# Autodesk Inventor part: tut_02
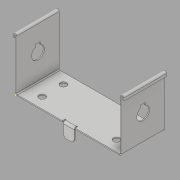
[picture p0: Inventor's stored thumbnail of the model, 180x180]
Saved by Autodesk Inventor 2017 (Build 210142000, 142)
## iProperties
Created: 2015-06
Part Number: tut_02
Material: Generic
Document SubType Name: Sheet Metal
Designer: Sandeep
Density: 1 g/cm^3
Sheet Metal Rule: Default_mm
Appearance: Default
Flat Pattern Width: 5.12619 cm
Flat Pattern Length: 20.443 cm
Flat Pattern Area: 104.795 cm^2
Sheet Metal Width: 51.262 mm
Sheet Metal Length: 204.430 mm
Sheet Metal Area: 10479.484 mm^2
Author: Sandeep
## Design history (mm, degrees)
sketch "Sketch1"
  geometry: 1 further point
node "Face1"
  sketch "Sketch2"
    geometry: L1 (0, 0)-(100, 0); L2 (100, 0)-(100, 40); L3 (100, 40)-(0, 40); L4 (0, 40)-(0, 0)
    constraints: 8 end point, 2 parallel, 1 horizontal, 1 perpendicular
    dimensions: "d0" = 100 distance between parallel lines of L2 L4; "d1" = 40 distance between parallel lines of L1 L3
hole "Hole1" diameter "d5" = 6; stored, may be unused: countersink angle "d9" = 90 deg, drill point angle "d11" = 118 deg; dims "d3" = 10, "d4" = 15, "d6" = 6, "d7" = 4, "d8" = 2, "d10" = 1 (= Thickness)
pattern_linear "Rectangular Pattern1" dims "d14" = 20
pattern_linear "Rectangular Pattern2" dims "d17" = 70
node "Flange1"
node "Flange2"
feature "Hem1" dims "d38" = 1 (= BendReliefWidth), "d39" = 0.5 (= BendReliefDepth), "d40" = 2 (= MinimumRemnant), "d41" = 1 (= BendRadius), "d42" = 4 (= 4 x Thickness), "d43" = 1 (= Thickness), "d44" = 0.5 (= 0.5 x d43), "SeamGap" = 0.01, "Thickness" = 1 (derived)
feature "Hem2" dims "d45" = 1 (= BendReliefWidth), "d46" = 0.5 (= BendReliefDepth), "d47" = 2 (= MinimumRemnant), "d48" = 1 (= BendRadius), "d49" = 4 (= 4 x Thickness), "d50" = 1 (= Thickness), "d51" = 0.5 (= 0.5 x d50), "SeamGap" = 0.01, "Thickness" = 1 (derived)
sketch "Sketch7"
  geometry: L1 (0, 40)-(0, 0) reference; L2 (48, 0)-(0, 0) reference; 2 further points
  dimensions: "d52" = 25 distance from line of point (25, 20) L1; "d53" = 20 distance from line of L2 point (25, 20)
feature "iFeature15:1" sketch "Sketch7"
sketch "Sketch8"
  geometry: L1 (17.2, 18)-(17.2, 22) reference; L2 (19.343, 18)-(17.2, 18) reference; L3 (17.2, 22)-(19.343, 22) reference; L4 (17.2, 18)-(17.2, 22) reference; L5 (17.2, 22)-(19.343, 22) reference; L6 (19.343, 18)-(17.2, 18) reference; L7 (48, 0)-(48, 40) reference; L8 (48, 40)-(1.5, 40) reference; L9 (48, 0)-(1.5, 0) reference; L10 (1.5, 40)-(1.5, 0) reference; A1 r 6 centre (25, 20) between (19.343, 18) and (19.343, 22) reference; A2 r 6 centre (25, 20) between (19.343, 18) and (19.343, 22) reference; 1 further point
feature "iFeature15:2" sketch "Sketch8"
node "Flange3"
feature "Corner Round1" dims "d78" = 3
workplane "Work Plane1"
mirror "Mirror1"
body "Solid1"
face "Plate1" dims "Thickness" = 1 (derived)
sketch "Sketch3"
  geometry: L1 through (20, 0) direction (-1, 0); L2 through (0, -25) direction (0, -1); L3 (0, -50)-(40, -50); L4 (40, -50)-(40, 0)
  constraints: 6 end point, 1 horizontal, 1 perpendicular, 1 vertical
face "Plate2" dims "d18" = 1 (= BendReliefWidth), "d19" = 0.5 (= BendReliefDepth), "d20" = 2 (= MinimumRemnant), "d21" = 1 (= BendRadius), "d22" = 50, "d23" = 90 deg, "d24" = 1 (= BendRadius), "d25" = 4 (= CornerReliefSize), "d26" = 1 (= GapSize), "d27" = 1 (= JacobiRadiusSize), "SeamGap" = 0.01, "Thickness" = 1 (derived)
bend "Bend1" dims "d18" = 1 (= BendReliefWidth), "d19" = 0.5 (= BendReliefDepth), "d20" = 2 (= MinimumRemnant), "d21" = 1 (= BendRadius), "d22" = 50, "d23" = 90 deg, "d24" = 1 (= BendRadius), "SeamGap" = 0.01, "Thickness" = 1 (derived)
feature "Corner1" dims "d22" = 50, "d23" = 90 deg, "d25" = 4 (= CornerReliefSize), "d26" = 1 (= GapSize), "d27" = 1 (= JacobiRadiusSize)
sketch "Sketch4"
  geometry: L1 through (20, 0) direction (-1, 5.47e-48); L2 through (0, -25) direction (-2.71e-32, -1); L3 (0, -50)-(40, -50); L4 (40, -50)-(40, 0)
  constraints: 6 end point, 1 horizontal, 1 perpendicular, 1 vertical
face "Plate3" dims "d28" = 1 (= BendReliefWidth), "d29" = 0.5 (= BendReliefDepth), "d30" = 2 (= MinimumRemnant), "d31" = 1 (= BendRadius), "d32" = 50, "d33" = 90 deg, "d34" = 1 (= BendRadius), "d35" = 4 (= CornerReliefSize), "d36" = 1 (= GapSize), "d37" = 1 (= JacobiRadiusSize), "SeamGap" = 0.01, "Thickness" = 1 (derived)
bend "Bend2" dims "d28" = 1 (= BendReliefWidth), "d29" = 0.5 (= BendReliefDepth), "d30" = 2 (= MinimumRemnant), "d31" = 1 (= BendRadius), "d32" = 50, "d33" = 90 deg, "d34" = 1 (= BendRadius), "SeamGap" = 0.01, "Thickness" = 1 (derived)
feature "Corner2" dims "d32" = 50, "d33" = 90 deg, "d35" = 4 (= CornerReliefSize), "d36" = 1 (= GapSize), "d37" = 1 (= JacobiRadiusSize)
node "Projected Loop1"
sketch "Sketch9"
  geometry: L1 (-53, 0)-(-43, 0); L2 (-43, 0)-(-43, 13); L3 (-43, 13)-(-53, 13); L4 (-53, 13)-(-53, 0)
  constraints: 8 end point
face "Plate4" dims "d67" = 1 (= BendReliefWidth), "d68" = 0.5 (= BendReliefDepth), "d69" = 2 (= MinimumRemnant), "d70" = 1 (= BendRadius), "d71" = 10, "d72" = 13, "d73" = 90 deg, "d74" = 1 (= BendRadius), "d75" = 4 (= CornerReliefSize), "d76" = 1 (= GapSize), "d77" = 1 (= JacobiRadiusSize), "SeamGap" = 0.01, "Thickness" = 1 (derived)
bend "Bend3" dims "d67" = 1 (= BendReliefWidth), "d68" = 0.5 (= BendReliefDepth), "d69" = 2 (= MinimumRemnant), "d70" = 1 (= BendRadius), "d72" = 13, "d73" = 90 deg, "d74" = 1 (= BendRadius), "SeamGap" = 0.01, "Thickness" = 1 (derived)
feature "Corner3" dims "d72" = 13, "d73" = 90 deg, "d75" = 4 (= CornerReliefSize), "d76" = 1 (= GapSize), "d77" = 1 (= JacobiRadiusSize)
sketch "Sketch5"
  geometry: L1 (1, 0)-(0, 0); L2 (-1, 0)-(-1, -2.5); L3 (-1, -2.5)-(-2, -2.5); L4 (-2, -2.5)-(-2, 0); A1 r 0.5 centre (-0.5, 0) between (0, 0) and (-1, 0); A2 r 1.5 centre (-0.5, 0) between (1, 0) and (-2, 0); 2 further points
  constraints: 8 end point, 4 point on circle
sketch "Sketch6"
  geometry: L1 (0, 0)-(1, 0); L2 (2, 0)-(2, -2.5); L3 (2, -2.5)-(3, -2.5); L4 (3, -2.5)-(3, 0); A1 r 0.5 centre (1.5, 0) between (2, 0) and (1, 0); A2 r 1.5 centre (1.5, 0) between (3, 0) and (0, 0); 2 further points
  constraints: 8 end point, 4 point on circle
feature "Definition1"
other parameters: "BendRadius" = 1 (= Thickness), "BendReliefWidth" = 1 (= Thickness), "BendReliefDepth" = 0.5 (= 0.5 x Thickness), "CornerReliefSize" = 4 (= 4 x Thickness), "MinimumRemnant" = 2 (= 2 x Thickness), "TransitionRadius" = 1 (= BendRadius), "JacobiRadiusSize" = 1 (= BendRadius), "GapSize" = 1 (= Thickness), "d2" = 1 (= BendRadius), "d66" = 90 deg, "d81" = 90 deg, "BendRadius" = 1, "BendReliefDepth" = 0.5, "BendReliefWidth" = 1, "CornerReliefSize" = 4, "GapSize" = 1, "JacobiRadiusSize" = 1, "MinimumRemnant" = 2, "Thickness" = 1, "TransitionRadius" = 1
